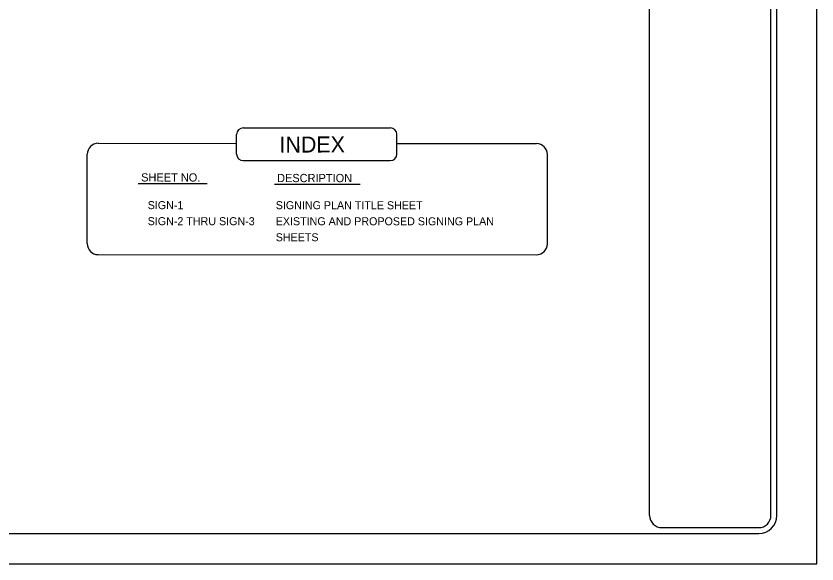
# Model space of a CAD drawing. Extents: x -2362 to 1945, y 0 to 1100.
# Drawn here: x 1039 to 1700, y 0 to 451 of the extents above; entities that cross this region are included whole.
import ezdxf

# ---------------------------------------------------------------- set-up
doc = ezdxf.new("R2010")
doc.units = 0
for name, color, linetype in [('Exist Utilities Power Test Hole SUE LOS A CELL', 7, 'Continuous'), ('Exist Utilities Telephone Test Hole SUE LOS A CELL', 7, 'Continuous'), ('Sheet_Title_Block_Text', 7, 'Continuous'), ('z - Construction', 7, 'Continuous')]:
    doc.layers.add(name, color=color, linetype=linetype)

msp = doc.modelspace()

# ---------------------------------------------------------------- linework, layer by layer
at = {"layer": 'Exist Utilities Telephone Test Hole SUE LOS A CELL'}
for p, q in [((1699.98, 0), (1699.98, 1100)), ((0, 0), (1699.98, 0))]:
    msp.add_line(p, q, dxfattribs=at)
at = {"layer": 'z - Construction'}
for p, q in [((1561.97, 39.96), (1562, 1059.93)), ((1662, 39.96), (1662, 1059.91)), ((1667, 39.99), (1667, 1059.91)), ((1221.4, 337.74), (1221.4, 353.76)), ((1353.56, 337.74), (1353.56, 353.76)), ((1107.27, 346.58), (1221.41, 346.53)), ((1353.57, 346.47), (1468.63, 346.42)), ((1098.14, 263.92), (1098.18, 337.5)), ((1477.68, 263.74), (1477.71, 337.32)), ((1140.18, 313.53), (1197.04, 313.5)), ((1252.71, 313.01), (1323.35, 312.98)), ((1107.23, 254.83), (1468.59, 254.66)), ((1571.99, 29.94), (1651.98, 29.94)), ((38.07, 24.99), (1652, 24.99))]:
    msp.add_line(p, q, dxfattribs=at)
for points in [[(1226.86, 359.21), (1348.11, 359.21)], [(1226.86, 332.28), (1348.11, 332.28)]]:
    msp.add_lwpolyline(points, dxfattribs=at)
for centre, radius, start, end in [((1226.86, 353.76), 5.45, 90, 180), ((1348.11, 353.76), 5.45, 360, 90), ((1107.26, 337.5), 9.09, 89.97341, 179.97341), ((1468.63, 337.33), 9.09, 359.97341, 89.97341), ((1226.86, 337.74), 5.45, 180, 270), ((1348.11, 337.74), 5.45, 270, 360), ((1107.23, 263.92), 9.09, 179.97341, 269.97341), ((1468.59, 263.75), 9.09, 269.97341, 359.97341), ((1571.99, 39.96), 10.02, 179.99864, 270), ((1651.98, 39.96), 10.02, 270, 360), ((1652, 39.99), 15, 270.00782, 0.00782)]:
    msp.add_arc(centre, radius, start, end, dxfattribs=at)

# ---------------------------------------------------------------- texts
at = {"layer": 'Exist Utilities Power Test Hole SUE LOS A CELL'}
for s, height, p in [('SHEET NO.', 6.771, (1142.65, 315.1)), ('DESCRIPTION', 6.7709, (1254.74, 314.58)), ('SIGN-1          ', 6.6, (1148.03, 292.31)), ('SIGNING PLAN TITLE SHEET', 6.6, (1253.63, 292.26)), ('SIGN-2 THRU SIGN-3', 6.6, (1148.02, 279.11)), ('EXISTING AND PROPOSED SIGNING PLAN', 6.6, (1253.62, 279.06)), ('SHEETS', 6.6, (1253.62, 265.86))]:
    msp.add_text(s, height=height, rotation=359.97341, dxfattribs=at).set_placement(p)
at = {"layer": 'Sheet_Title_Block_Text'}
msp.add_text('INDEX', height=13.2, rotation=0.15565, dxfattribs=at).set_placement((1256.76, 338.89))

doc.saveas('drawing.dxf')
